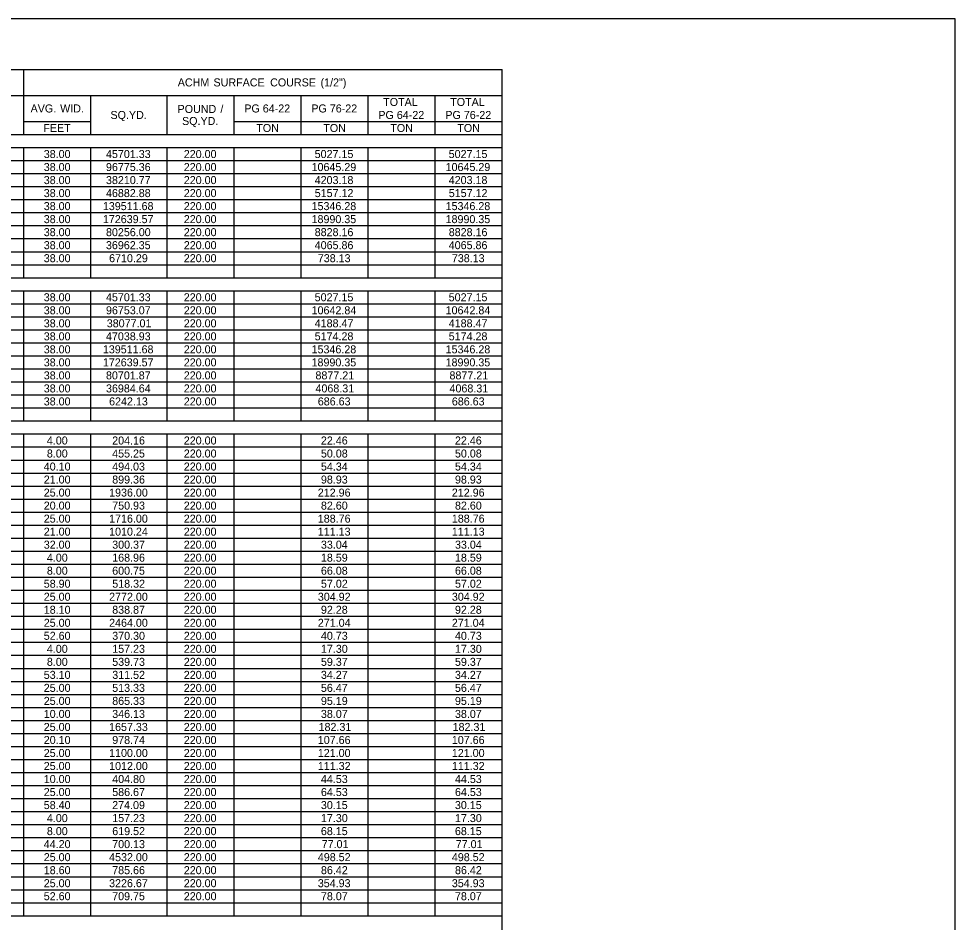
# Model space of a CAD drawing. Extents: x 2261867 to 2275370, y -3124789 to -3122260.
# Drawn here: x 2270088 to 2270720, y -3124232 to -3123623 of the extents above; entities that cross this region are included whole.
import ezdxf

# ---------------------------------------------------------------- set-up
doc = ezdxf.new("R2010")
doc.units = 0
doc.layers.add('Default', color=7, linetype='Continuous')
doc.layers.add('DSN_DRFT_Named-Boundary', color=7, linetype='Continuous')

msp = doc.modelspace()

# ---------------------------------------------------------------- linework, layer by layer
at = {"layer": 'Default'}
for p, q in [((2269400.16, -3123657.37), (2270414.11, -3123657.37)), ((2270091.63, -3123701.24), (2270091.63, -3123657.37)), ((2270414.11, -3124701.59), (2270414.11, -3123657.37)), ((2270414.11, -3123701.24), (2270414.11, -3123657.37)), ((2269814.34, -3123674.92), (2270414.11, -3123674.92)), ((2270091.63, -3123674.92), (2270323.73, -3123674.92)), ((2270136.82, -3123701.24), (2270136.82, -3123674.92)), ((2270188.16, -3123701.24), (2270188.16, -3123674.92)), ((2270233.35, -3123701.24), (2270233.35, -3123674.92)), ((2270278.54, -3123701.24), (2270278.54, -3123674.92)), ((2270323.73, -3123701.24), (2270323.73, -3123674.92)), ((2270368.92, -3123701.24), (2270368.92, -3123674.92)), ((2270091.63, -3123692.47), (2270136.82, -3123692.47)), ((2270091.63, -3123701.24), (2270091.63, -3123692.47)), ((2270136.82, -3123701.24), (2270136.82, -3123692.47)), ((2270233.35, -3123692.47), (2270414.11, -3123692.47)), ((2269400.16, -3123701.24), (2270414.11, -3123701.24)), ((2270001.25, -3123701.24), (2270136.82, -3123701.24)), ((2270136.82, -3123701.24), (2270414.11, -3123701.24)), ((2269400.16, -3123710.02), (2270414.11, -3123710.02)), ((2270091.63, -3123797.77), (2270091.63, -3123710.02)), ((2270091.63, -3123797.77), (2270091.63, -3123710.02)), ((2270136.82, -3123797.77), (2270136.82, -3123710.02)), ((2270136.82, -3123797.77), (2270136.82, -3123710.02)), ((2270188.16, -3123797.77), (2270188.16, -3123710.02)), ((2270188.16, -3123797.77), (2270188.16, -3123710.02)), ((2270233.35, -3123797.77), (2270233.35, -3123710.02)), ((2270233.35, -3123797.77), (2270233.35, -3123710.02)), ((2270278.54, -3123797.77), (2270278.54, -3123710.02)), ((2270278.54, -3123797.77), (2270278.54, -3123710.02)), ((2270323.73, -3123797.77), (2270323.73, -3123710.02)), ((2270323.73, -3123797.77), (2270323.73, -3123710.02)), ((2270368.92, -3123797.77), (2270368.92, -3123710.02)), ((2270368.92, -3123797.77), (2270368.92, -3123710.02)), ((2270414.11, -3123797.77), (2270414.11, -3123710.02)), ((2269400.16, -3123718.79), (2270414.11, -3123718.79)), ((2269400.16, -3123727.57), (2270414.11, -3123727.57)), ((2269400.16, -3123736.34), (2270414.11, -3123736.34)), ((2269400.16, -3123745.12), (2270414.11, -3123745.12)), ((2269400.16, -3123753.89), (2270414.11, -3123753.89)), ((2269400.16, -3123762.67), (2270414.11, -3123762.67)), ((2269400.16, -3123771.44), (2270414.11, -3123771.44)), ((2269400.16, -3123780.22), (2270414.11, -3123780.22)), ((2269400.16, -3123788.99), (2270414.11, -3123788.99)), ((2269400.16, -3123797.77), (2270414.11, -3123797.77)), ((2269400.16, -3123797.77), (2270414.11, -3123797.77)), ((2269400.16, -3123806.54), (2270414.11, -3123806.54)), ((2270091.63, -3123894.29), (2270091.63, -3123806.54)), ((2270091.63, -3123894.29), (2270091.63, -3123806.54)), ((2270136.82, -3123894.29), (2270136.82, -3123806.54)), ((2270136.82, -3123894.29), (2270136.82, -3123806.54)), ((2270188.16, -3123894.29), (2270188.16, -3123806.54)), ((2270188.16, -3123894.29), (2270188.16, -3123806.54)), ((2270233.35, -3123894.29), (2270233.35, -3123806.54)), ((2270233.35, -3123894.29), (2270233.35, -3123806.54)), ((2270278.54, -3123894.29), (2270278.54, -3123806.54)), ((2270278.54, -3123894.29), (2270278.54, -3123806.54)), ((2270323.73, -3123894.29), (2270323.73, -3123806.54)), ((2270323.73, -3123894.29), (2270323.73, -3123806.54)), ((2270368.92, -3123894.29), (2270368.92, -3123806.54)), ((2270368.92, -3123894.29), (2270368.92, -3123806.54)), ((2270414.11, -3123894.29), (2270414.11, -3123806.54)), ((2269400.16, -3123815.32), (2270414.11, -3123815.32)), ((2269400.16, -3123824.09), (2270414.11, -3123824.09)), ((2269400.16, -3123832.87), (2270414.11, -3123832.87)), ((2269400.16, -3123841.64), (2270414.11, -3123841.64)), ((2269400.16, -3123850.42), (2270414.11, -3123850.42)), ((2269400.16, -3123859.19), (2270414.11, -3123859.19)), ((2269400.16, -3123867.97), (2270414.11, -3123867.97)), ((2269400.16, -3123876.74), (2270414.11, -3123876.74)), ((2269400.16, -3123885.52), (2270414.11, -3123885.52)), ((2269400.16, -3123894.29), (2270414.11, -3123894.29)), ((2269400.16, -3123894.29), (2270414.11, -3123894.29)), ((2269400.16, -3123903.07), (2270414.11, -3123903.07)), ((2270091.63, -3124227.74), (2270091.63, -3123903.07)), ((2270091.63, -3124227.74), (2270091.63, -3123903.07)), ((2270136.82, -3124227.74), (2270136.82, -3123903.07)), ((2270136.82, -3124227.74), (2270136.82, -3123903.07)), ((2270188.16, -3124227.74), (2270188.16, -3123903.07)), ((2270188.16, -3124227.74), (2270188.16, -3123903.07)), ((2270233.35, -3124227.74), (2270233.35, -3123903.07)), ((2270233.35, -3124227.74), (2270233.35, -3123903.07)), ((2270278.54, -3124227.74), (2270278.54, -3123903.07)), ((2270278.54, -3124227.74), (2270278.54, -3123903.07)), ((2270323.73, -3124227.74), (2270323.73, -3123903.07)), ((2270323.73, -3124227.74), (2270323.73, -3123903.07)), ((2270368.92, -3124227.74), (2270368.92, -3123903.07)), ((2270368.92, -3124227.74), (2270368.92, -3123903.07)), ((2270414.11, -3124227.74), (2270414.11, -3123903.07)), ((2269400.16, -3123911.84), (2270414.11, -3123911.84)), ((2269400.16, -3123920.62), (2270414.11, -3123920.62)), ((2269400.16, -3123929.39), (2270414.11, -3123929.39)), ((2269400.16, -3123938.17), (2270414.11, -3123938.17)), ((2269400.16, -3123946.94), (2270414.11, -3123946.94)), ((2269400.16, -3123955.72), (2270414.11, -3123955.72)), ((2269400.16, -3123964.49), (2270414.11, -3123964.49)), ((2269400.16, -3123973.27), (2270414.11, -3123973.27)), ((2269400.16, -3123982.04), (2270414.11, -3123982.04)), ((2269400.16, -3123990.82), (2270414.11, -3123990.82)), ((2269400.16, -3123999.59), (2270414.11, -3123999.59)), ((2269400.16, -3124008.37), (2270414.11, -3124008.37)), ((2269400.16, -3124017.14), (2270414.11, -3124017.14)), ((2269400.16, -3124025.92), (2270414.11, -3124025.92)), ((2269400.16, -3124034.69), (2270414.11, -3124034.69)), ((2269400.16, -3124043.47), (2270414.11, -3124043.47)), ((2269400.16, -3124052.24), (2270414.11, -3124052.24)), ((2269400.16, -3124061.02), (2270414.11, -3124061.02)), ((2269400.16, -3124069.79), (2270414.11, -3124069.79)), ((2269400.16, -3124078.57), (2270414.11, -3124078.57)), ((2269400.16, -3124087.34), (2270414.11, -3124087.34)), ((2269400.16, -3124096.12), (2270414.11, -3124096.12)), ((2269400.16, -3124104.89), (2270414.11, -3124104.89)), ((2269400.16, -3124113.67), (2270414.11, -3124113.67)), ((2269400.16, -3124122.44), (2270414.11, -3124122.44)), ((2269400.16, -3124131.22), (2270414.11, -3124131.22)), ((2269400.16, -3124139.99), (2270414.11, -3124139.99)), ((2269400.16, -3124148.77), (2270414.11, -3124148.77)), ((2269400.16, -3124157.54), (2270414.11, -3124157.54)), ((2269400.16, -3124166.32), (2270414.11, -3124166.32)), ((2269400.16, -3124175.09), (2270414.11, -3124175.09)), ((2269400.16, -3124183.87), (2270414.11, -3124183.87)), ((2269400.16, -3124192.64), (2270414.11, -3124192.64)), ((2269400.16, -3124201.42), (2270414.11, -3124201.42)), ((2269400.16, -3124210.19), (2270414.11, -3124210.19)), ((2269949.92, -3124218.97), (2270414.11, -3124218.97)), ((2269400.16, -3124227.74), (2270414.11, -3124227.74)), ((2269949.92, -3124227.74), (2270414.11, -3124227.74))]:
    msp.add_line(p, q, dxfattribs=at)
at = {"layer": 'DSN_DRFT_Named-Boundary'}
msp.add_lwpolyline([(2269094.64, -3124789.38), (2270719.64, -3124789.38), (2270719.64, -3123623.23), (2269094.64, -3123623.23)], close=True, dxfattribs=at)

# ---------------------------------------------------------------- texts
at = {"layer": 'Default'}
for s, p in [('ACHM', (2270195.33, -3123668.84)), (' SURFACE', (2270217.43, -3123668.84)), (' COURSE', (2270255.62, -3123668.84)), (' (1/2")', (2270289.63, -3123668.84)), ('TOTAL', (2270333.87, -3123682.01)), ('TOTAL', (2270379.06, -3123682.01)), ('AVG.', (2270096.09, -3123686.39)), (' WID.', (2270114.02, -3123686.39)), ('SQ.YD.', (2270149.96, -3123690.78)), ('POUND', (2270195.21, -3123686.73)), (' /', (2270222.09, -3123686.73)), ('PG', (2270240.22, -3123686.39)), (' 64-22', (2270250.66, -3123686.39)), ('PG', (2270285.41, -3123686.39)), (' 76-22', (2270295.86, -3123686.39)), ('PG', (2270330.6, -3123690.78)), (' 64-22', (2270341.05, -3123690.78)), ('PG', (2270375.79, -3123690.78)), (' 76-22', (2270386.24, -3123690.78)), ('SQ.YD.', (2270198.22, -3123694.83)), ('FEET', (2270104.66, -3123699.56)), ('TON', (2270248.28, -3123699.56)), ('TON', (2270293.47, -3123699.56)), ('TON', (2270338.66, -3123699.56)), ('TON', (2270383.86, -3123699.56)), ('38.00', (2270104.97, -3123717.11)), ('45701.33', (2270146.93, -3123717.11)), ('220.00', (2270199.4, -3123717.11)), ('5027.15', (2270287.66, -3123717.11)), ('5027.15', (2270378.04, -3123717.11)), ('38.00', (2270104.97, -3123725.88)), ('96775.36', (2270146.93, -3123725.88)), ('220.00', (2270199.4, -3123725.88)), ('10645.29', (2270285.57, -3123725.88)), ('10645.29', (2270375.96, -3123725.88)), ('38.00', (2270104.97, -3123734.66)), ('38210.77', (2270146.93, -3123734.66)), ('220.00', (2270199.4, -3123734.66)), ('4203.18', (2270287.67, -3123734.66)), ('4203.18', (2270378.05, -3123734.66)), ('38.00', (2270104.97, -3123743.43)), ('46882.88', (2270146.93, -3123743.43)), ('220.00', (2270199.4, -3123743.43)), ('5157.12', (2270287.7, -3123743.43)), ('5157.12', (2270378.09, -3123743.43)), ('38.00', (2270104.97, -3123752.21)), ('139511.68', (2270144.83, -3123752.21)), ('220.00', (2270199.4, -3123752.21)), ('15346.28', (2270285.57, -3123752.21)), ('15346.28', (2270375.96, -3123752.21)), ('38.00', (2270104.97, -3123760.98)), ('172639.57', (2270144.84, -3123760.98)), ('220.00', (2270199.4, -3123760.98)), ('18990.35', (2270285.56, -3123760.98)), ('18990.35', (2270375.94, -3123760.98)), ('38.00', (2270104.97, -3123769.76)), ('80256.00', (2270146.94, -3123769.76)), ('220.00', (2270199.4, -3123769.76)), ('8828.16', (2270287.68, -3123769.76)), ('8828.16', (2270378.06, -3123769.76)), ('38.00', (2270104.97, -3123778.53)), ('36962.35', (2270146.91, -3123778.53)), ('220.00', (2270199.4, -3123778.53)), ('4065.86', (2270287.68, -3123778.53)), ('4065.86', (2270378.06, -3123778.53)), ('38.00', (2270104.97, -3123787.31)), ('6710.29', (2270149.03, -3123787.31)), ('220.00', (2270199.4, -3123787.31)), ('738.13', (2270289.77, -3123787.31)), ('738.13', (2270380.16, -3123787.31)), ('38.00', (2270104.97, -3123813.63)), ('45701.33', (2270146.93, -3123813.63)), ('220.00', (2270199.4, -3123813.63)), ('5027.15', (2270287.66, -3123813.63)), ('5027.15', (2270378.04, -3123813.63)), ('38.00', (2270104.97, -3123822.41)), ('96753.07', (2270146.93, -3123822.41)), ('220.00', (2270199.4, -3123822.41)), ('10642.84', (2270285.59, -3123822.41)), ('10642.84', (2270375.97, -3123822.41)), ('38.00', (2270104.97, -3123831.18)), ('38077.01', (2270147.46, -3123831.18)), ('220.00', (2270199.4, -3123831.18)), ('4188.47', (2270287.68, -3123831.18)), ('4188.47', (2270378.06, -3123831.18)), ('38.00', (2270104.97, -3123839.96)), ('47038.93', (2270146.93, -3123839.96)), ('220.00', (2270199.4, -3123839.96)), ('5174.28', (2270287.67, -3123839.96)), ('5174.28', (2270378.05, -3123839.96)), ('38.00', (2270104.97, -3123848.73)), ('139511.68', (2270144.83, -3123848.73)), ('220.00', (2270199.4, -3123848.73)), ('15346.28', (2270285.57, -3123848.73)), ('15346.28', (2270375.96, -3123848.73)), ('38.00', (2270104.97, -3123857.51)), ('172639.57', (2270144.84, -3123857.51)), ('220.00', (2270199.4, -3123857.51)), ('18990.35', (2270285.56, -3123857.51)), ('18990.35', (2270375.94, -3123857.51)), ('38.00', (2270104.97, -3123866.28)), ('80701.87', (2270146.93, -3123866.28)), ('220.00', (2270199.4, -3123866.28)), ('8877.21', (2270288.2, -3123866.28)), ('8877.21', (2270378.58, -3123866.28)), ('38.00', (2270104.97, -3123875.06)), ('36984.64', (2270146.95, -3123875.06)), ('220.00', (2270199.4, -3123875.06)), ('4068.31', (2270288.2, -3123875.06)), ('4068.31', (2270378.58, -3123875.06)), ('38.00', (2270104.97, -3123883.83)), ('6242.13', (2270149.03, -3123883.83)), ('220.00', (2270199.4, -3123883.83)), ('686.63', (2270289.77, -3123883.83)), ('686.63', (2270380.16, -3123883.83)), ('4.00', (2270107.07, -3123910.16)), ('204.16', (2270151.13, -3123910.16)), ('220.00', (2270199.4, -3123910.16)), ('22.46', (2270291.87, -3123910.16)), ('22.46', (2270382.25, -3123910.16)), ('8.00', (2270107.07, -3123918.93)), ('455.25', (2270151.11, -3123918.93)), ('220.00', (2270199.4, -3123918.93)), ('50.08', (2270291.87, -3123918.93)), ('50.08', (2270382.25, -3123918.93)), ('40.10', (2270104.97, -3123927.71)), ('494.03', (2270151.13, -3123927.71)), ('220.00', (2270199.4, -3123927.71)), ('54.34', (2270291.88, -3123927.71)), ('54.34', (2270382.26, -3123927.71)), ('21.00', (2270104.97, -3123936.48)), ('899.36', (2270151.13, -3123936.48)), ('220.00', (2270199.4, -3123936.48)), ('98.93', (2270291.87, -3123936.48)), ('98.93', (2270382.25, -3123936.48)), ('25.00', (2270104.97, -3123945.26)), ('1936.00', (2270149.04, -3123945.26)), ('220.00', (2270199.4, -3123945.26)), ('212.96', (2270289.77, -3123945.26)), ('212.96', (2270380.16, -3123945.26)), ('20.00', (2270104.97, -3123954.03)), ('750.93', (2270151.13, -3123954.03)), ('220.00', (2270199.4, -3123954.03)), ('82.60', (2270291.88, -3123954.03)), ('82.60', (2270382.26, -3123954.03)), ('25.00', (2270104.97, -3123962.81)), ('1716.00', (2270149.04, -3123962.81)), ('220.00', (2270199.4, -3123962.81)), ('188.76', (2270289.77, -3123962.81)), ('188.76', (2270380.16, -3123962.81)), ('21.00', (2270104.97, -3123971.58)), ('1010.24', (2270149.04, -3123971.58)), ('220.00', (2270199.4, -3123971.58)), ('111.13', (2270289.77, -3123971.58)), ('111.13', (2270380.16, -3123971.58)), ('32.00', (2270104.97, -3123980.36)), ('300.37', (2270151.13, -3123980.36)), ('220.00', (2270199.4, -3123980.36)), ('33.04', (2270291.88, -3123980.36)), ('33.04', (2270382.26, -3123980.36)), ('4.00', (2270107.07, -3123989.13)), ('168.96', (2270151.13, -3123989.13)), ('220.00', (2270199.4, -3123989.13)), ('18.59', (2270291.87, -3123989.13)), ('18.59', (2270382.25, -3123989.13)), ('8.00', (2270107.07, -3123997.91)), ('600.75', (2270151.11, -3123997.91)), ('220.00', (2270199.4, -3123997.91)), ('66.08', (2270291.87, -3123997.91)), ('66.08', (2270382.25, -3123997.91)), ('58.90', (2270104.97, -3124006.68)), ('518.32', (2270151.16, -3124006.68)), ('220.00', (2270199.4, -3124006.68)), ('57.02', (2270291.9, -3124006.68)), ('57.02', (2270382.28, -3124006.68)), ('25.00', (2270104.97, -3124015.46)), ('2772.00', (2270149.04, -3124015.46)), ('220.00', (2270199.4, -3124015.46)), ('304.92', (2270289.8, -3124015.46)), ('304.92', (2270380.18, -3124015.46)), ('18.10', (2270104.97, -3124024.23)), ('838.87', (2270151.13, -3124024.23)), ('220.00', (2270199.4, -3124024.23)), ('92.28', (2270291.87, -3124024.23)), ('92.28', (2270382.25, -3124024.23)), ('25.00', (2270104.97, -3124033.01)), ('2464.00', (2270149.04, -3124033.01)), ('220.00', (2270199.4, -3124033.01)), ('271.04', (2270289.79, -3124033.01)), ('271.04', (2270380.17, -3124033.01)), ('52.60', (2270104.97, -3124041.78)), ('370.30', (2270151.14, -3124041.78)), ('220.00', (2270199.4, -3124041.78)), ('40.73', (2270291.87, -3124041.78)), ('40.73', (2270382.25, -3124041.78)), ('4.00', (2270107.07, -3124050.56)), ('157.23', (2270151.13, -3124050.56)), ('220.00', (2270199.4, -3124050.56)), ('17.30', (2270291.88, -3124050.56)), ('17.30', (2270382.26, -3124050.56)), ('8.00', (2270107.07, -3124059.33)), ('539.73', (2270151.13, -3124059.33)), ('220.00', (2270199.4, -3124059.33)), ('59.37', (2270291.87, -3124059.33)), ('59.37', (2270382.25, -3124059.33)), ('53.10', (2270104.97, -3124068.11)), ('311.52', (2270151.16, -3124068.11)), ('220.00', (2270199.4, -3124068.11)), ('34.27', (2270291.87, -3124068.11)), ('34.27', (2270382.25, -3124068.11)), ('25.00', (2270104.97, -3124076.88)), ('513.33', (2270151.13, -3124076.88)), ('220.00', (2270199.4, -3124076.88)), ('56.47', (2270291.87, -3124076.88)), ('56.47', (2270382.25, -3124076.88)), ('25.00', (2270104.97, -3124085.66)), ('865.33', (2270151.13, -3124085.66)), ('220.00', (2270199.4, -3124085.66)), ('95.19', (2270291.87, -3124085.66)), ('95.19', (2270382.25, -3124085.66)), ('10.00', (2270104.97, -3124094.43)), ('346.13', (2270151.13, -3124094.43)), ('220.00', (2270199.4, -3124094.43)), ('38.07', (2270291.87, -3124094.43)), ('38.07', (2270382.25, -3124094.43)), ('25.00', (2270104.97, -3124103.21)), ('1657.33', (2270149.03, -3124103.21)), ('220.00', (2270199.4, -3124103.21)), ('182.31', (2270290.3, -3124103.21)), ('182.31', (2270380.68, -3124103.21)), ('20.10', (2270104.97, -3124111.98)), ('978.74', (2270151.14, -3124111.98)), ('220.00', (2270199.4, -3124111.98)), ('107.66', (2270289.77, -3124111.98)), ('107.66', (2270380.16, -3124111.98)), ('25.00', (2270104.97, -3124120.76)), ('1100.00', (2270149.04, -3124120.76)), ('220.00', (2270199.4, -3124120.76)), ('121.00', (2270289.78, -3124120.76)), ('121.00', (2270380.17, -3124120.76)), ('25.00', (2270104.97, -3124129.53)), ('1012.00', (2270149.04, -3124129.53)), ('220.00', (2270199.4, -3124129.53)), ('111.32', (2270289.8, -3124129.53)), ('111.32', (2270380.18, -3124129.53)), ('10.00', (2270104.97, -3124138.31)), ('404.80', (2270151.14, -3124138.31)), ('220.00', (2270199.4, -3124138.31)), ('44.53', (2270291.87, -3124138.31)), ('44.53', (2270382.25, -3124138.31)), ('25.00', (2270104.97, -3124147.08)), ('586.67', (2270151.13, -3124147.08)), ('220.00', (2270199.4, -3124147.08)), ('64.53', (2270291.87, -3124147.08)), ('64.53', (2270382.25, -3124147.08)), ('58.40', (2270104.97, -3124155.86)), ('274.09', (2270151.12, -3124155.86)), ('220.00', (2270199.4, -3124155.86)), ('30.15', (2270291.85, -3124155.86)), ('30.15', (2270382.23, -3124155.86)), ('4.00', (2270107.07, -3124164.63)), ('157.23', (2270151.13, -3124164.63)), ('220.00', (2270199.4, -3124164.63)), ('17.30', (2270291.88, -3124164.63)), ('17.30', (2270382.26, -3124164.63)), ('8.00', (2270107.07, -3124173.41)), ('619.52', (2270151.16, -3124173.41)), ('220.00', (2270199.4, -3124173.41)), ('68.15', (2270291.85, -3124173.41)), ('68.15', (2270382.23, -3124173.41)), ('44.20', (2270104.97, -3124182.18)), ('700.13', (2270151.13, -3124182.18)), ('220.00', (2270199.4, -3124182.18)), ('77.01', (2270292.39, -3124182.18)), ('77.01', (2270382.78, -3124182.18)), ('25.00', (2270104.97, -3124190.96)), ('4532.00', (2270149.04, -3124190.96)), ('220.00', (2270199.4, -3124190.96)), ('498.52', (2270289.8, -3124190.96)), ('498.52', (2270380.18, -3124190.96)), ('18.60', (2270104.97, -3124199.73)), ('785.66', (2270151.13, -3124199.73)), ('220.00', (2270199.4, -3124199.73)), ('86.42', (2270291.9, -3124199.73)), ('86.42', (2270382.28, -3124199.73)), ('25.00', (2270104.97, -3124208.51)), ('3226.67', (2270149.03, -3124208.51)), ('220.00', (2270199.4, -3124208.51)), ('354.93', (2270289.77, -3124208.51)), ('354.93', (2270380.16, -3124208.51)), ('52.60', (2270104.97, -3124217.28)), ('709.75', (2270151.11, -3124217.28)), ('220.00', (2270199.4, -3124217.28)), ('78.07', (2270291.87, -3124217.28)), ('78.07', (2270382.25, -3124217.28))]:
    msp.add_text(s, height=5.4, dxfattribs=at).set_placement(p)

doc.saveas('drawing.dxf')
